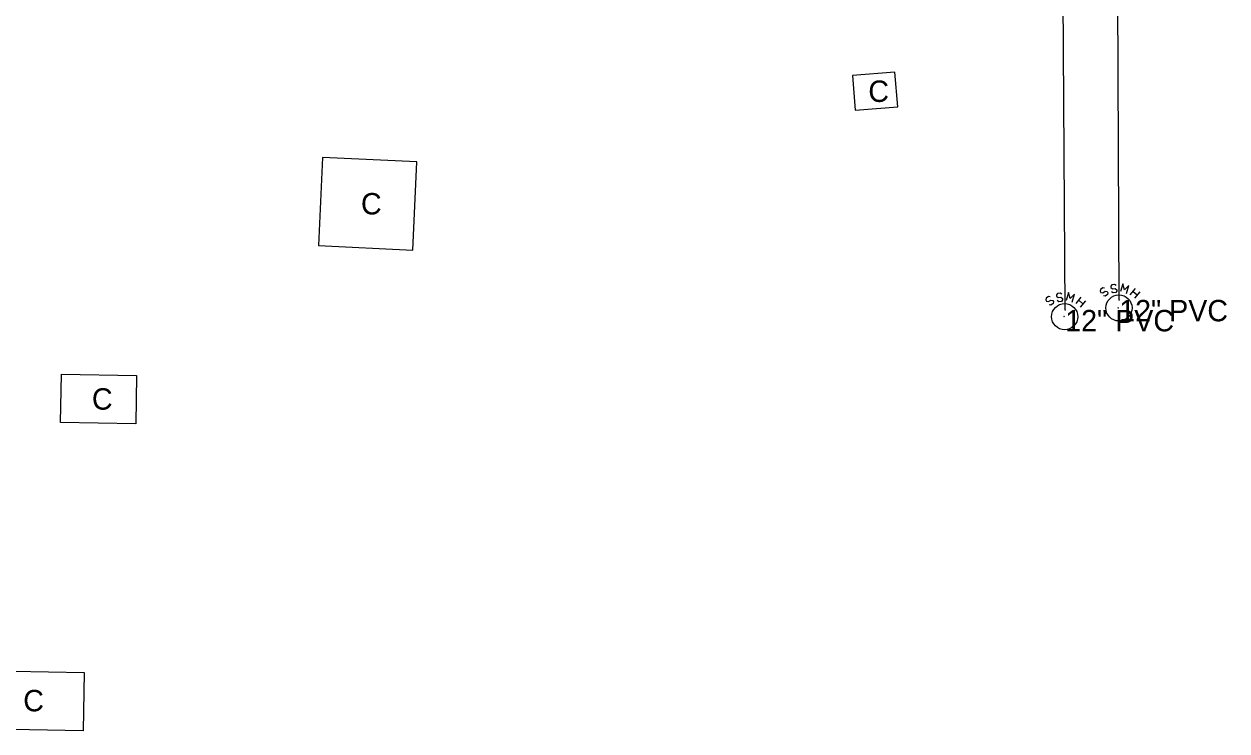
# Model space of a CAD drawing. Extents: x 1304270 to 1306561, y 1876019 to 1876752.
# Drawn here: x 1306055.3 to 1306336.2, y 1876082.9 to 1876248 of the extents above; entities that cross this region are included whole.
import ezdxf

# ---------------------------------------------------------------- set-up
doc = ezdxf.new("R2010")
doc.units = 0
for name, color, linetype in [('S_BUILDING', 7, 'Continuous'), ('S_BUILDING_ANNOT', 7, 'Continuous'), ('S_SANITARY_SEWER', 7, 'Continuous'), ('S_SANITARY_SEWER_ANNOT', 7, 'Continuous'), ('S_UTL_PT_SYM', 7, 'Continuous')]:
    doc.layers.add(name, color=color, linetype=linetype)

msp = doc.modelspace()

# ---------------------------------------------------------------- linework, layer by layer
at = {"layer": 'S_BUILDING'}
for points in [[(1306249.4, 1876227.81), (1306259.32, 1876228.62), (1306258.66, 1876236.75), (1306248.74, 1876235.94)], [(1306125.01, 1876216.82), (1306124.03, 1876196.22), (1306146.07, 1876195.17), (1306147.06, 1876215.77)], [(1306064.03, 1876166.22), (1306081.59, 1876165.91), (1306081.39, 1876154.62), (1306063.83, 1876154.93)], [(1306044.25, 1876097.05), (1306069.37, 1876096.57), (1306069.11, 1876082.9), (1306043.99, 1876083.38)]]:
    msp.add_lwpolyline(points, close=True, dxfattribs=at)
at = {"layer": 'S_SANITARY_SEWER'}
for p, q in [((1306298.44, 1876181.2), (1306296.96, 1876415.93)), ((1306311.04, 1876183.54), (1306310.05, 1876415.77)), ((1306293.98, 1876183.93), (1306293.91, 1876183.54)), ((1306294.53, 1876184.32), (1306293.98, 1876183.93)), ((1306294.95, 1876184.24), (1306294.53, 1876184.32)), ((1306300.96, 1876182.69), (1306302.2, 1876184.16)), ((1306306.67, 1876185.97), (1306306.59, 1876185.59)), ((1306306.59, 1876185.59), (1306306.78, 1876185.31)), ((1306307.21, 1876186.36), (1306306.67, 1876185.97)), ((1306306.78, 1876185.31), (1306307.21, 1876185.2)), ((1306307.63, 1876186.28), (1306307.21, 1876186.36)), ((1306307.21, 1876185.2), (1306307.75, 1876185.55)), ((1306307.75, 1876184.38), (1306307.36, 1876184.46)), ((1306307.75, 1876185.55), (1306308.22, 1876185.47)), ((1306308.29, 1876184.77), (1306307.75, 1876184.38)), ((1306308.22, 1876185.47), (1306308.37, 1876185.2)), ((1306308.37, 1876185.2), (1306308.29, 1876184.77)), ((1306313.64, 1876184.73), (1306314.88, 1876186.21)), ((1306314.3, 1876185.51), (1306315.27, 1876184.69)), ((1306315.85, 1876185.39), (1306314.61, 1876183.92)), ((1306293.91, 1876183.54), (1306294.1, 1876183.27)), ((1306294.1, 1876183.27), (1306294.53, 1876183.16)), ((1306294.53, 1876183.16), (1306295.07, 1876183.5)), ((1306295.07, 1876182.34), (1306294.68, 1876182.42)), ((1306295.07, 1876183.5), (1306295.53, 1876183.43)), ((1306295.61, 1876182.73), (1306295.07, 1876182.34)), ((1306295.53, 1876183.43), (1306295.69, 1876183.16)), ((1306295.69, 1876183.16), (1306295.61, 1876182.73)), ((1306301.62, 1876183.47), (1306302.59, 1876182.65)), ((1306303.17, 1876183.35), (1306301.93, 1876181.88))]:
    msp.add_line(p, q, dxfattribs=at)
for points in [[(1306310.31, 1876186.9), (1306309.96, 1876187.17), (1306309.3, 1876187.1), (1306309.07, 1876186.75), (1306309.11, 1876186.44), (1306309.46, 1876186.13), (1306310.08, 1876186.24), (1306310.46, 1876185.93), (1306310.5, 1876185.62), (1306310.23, 1876185.24), (1306309.61, 1876185.16), (1306309.26, 1876185.43)], [(1306312.75, 1876185.04), (1306313.29, 1876186.9), (1306312.25, 1876185.9), (1306311.86, 1876187.33), (1306311.32, 1876185.47)], [(1306297.63, 1876184.86), (1306297.28, 1876185.13), (1306296.62, 1876185.05), (1306296.39, 1876184.71), (1306296.43, 1876184.4), (1306296.77, 1876184.09), (1306297.39, 1876184.2), (1306297.78, 1876183.89), (1306297.82, 1876183.58), (1306297.55, 1876183.19), (1306296.93, 1876183.12), (1306296.58, 1876183.39)], [(1306300.07, 1876183), (1306300.61, 1876184.86), (1306299.56, 1876183.85), (1306299.18, 1876185.29), (1306298.63, 1876183.43)]]:
    msp.add_lwpolyline(points, dxfattribs=at)
for centre in [(1306310.99, 1876181.67), (1306298.31, 1876179.63)]:
    msp.add_circle(centre, 3.05, dxfattribs=at)
at = {"layer": 'S_UTL_PT_SYM'}
for points in [[(1306298.44, 1876181.2), (1306298.44, 1876181.25), (1306298.44, 1876181.2), (1306298.39, 1876181.2), (1306298.44, 1876181.2), (1306298.44, 1876181.15), (1306298.44, 1876181.2), (1306298.49, 1876181.2)], [(1306310.82, 1876181.69), (1306310.82, 1876181.74), (1306310.82, 1876181.69), (1306310.77, 1876181.69), (1306310.82, 1876181.69), (1306310.82, 1876181.64), (1306310.82, 1876181.69), (1306310.87, 1876181.69)], [(1306311.04, 1876183.54), (1306311.04, 1876183.59), (1306311.04, 1876183.54), (1306310.99, 1876183.54), (1306311.04, 1876183.54), (1306311.04, 1876183.49), (1306311.04, 1876183.54), (1306311.09, 1876183.54)], [(1306298.18, 1876179.64), (1306298.18, 1876179.69), (1306298.18, 1876179.64), (1306298.13, 1876179.64), (1306298.18, 1876179.64), (1306298.18, 1876179.59), (1306298.18, 1876179.64), (1306298.23, 1876179.64)]]:
    msp.add_lwpolyline(points, dxfattribs=at)

# ---------------------------------------------------------------- texts
at = {"layer": 'S_BUILDING_ANNOT'}
for p in [(1306252.46, 1876229.77), (1306133.99, 1876203.5), (1306071.16, 1876157.92), (1306055.12, 1876087.48)]:
    msp.add_text('C', height=5, dxfattribs=at).set_placement(p)
at = {"layer": 'S_SANITARY_SEWER_ANNOT'}
for p in [(1306298.44, 1876176.2), (1306311.04, 1876178.54)]:
    msp.add_text('12" PVC', height=5, dxfattribs=at).set_placement(p)

doc.saveas('drawing.dxf')
